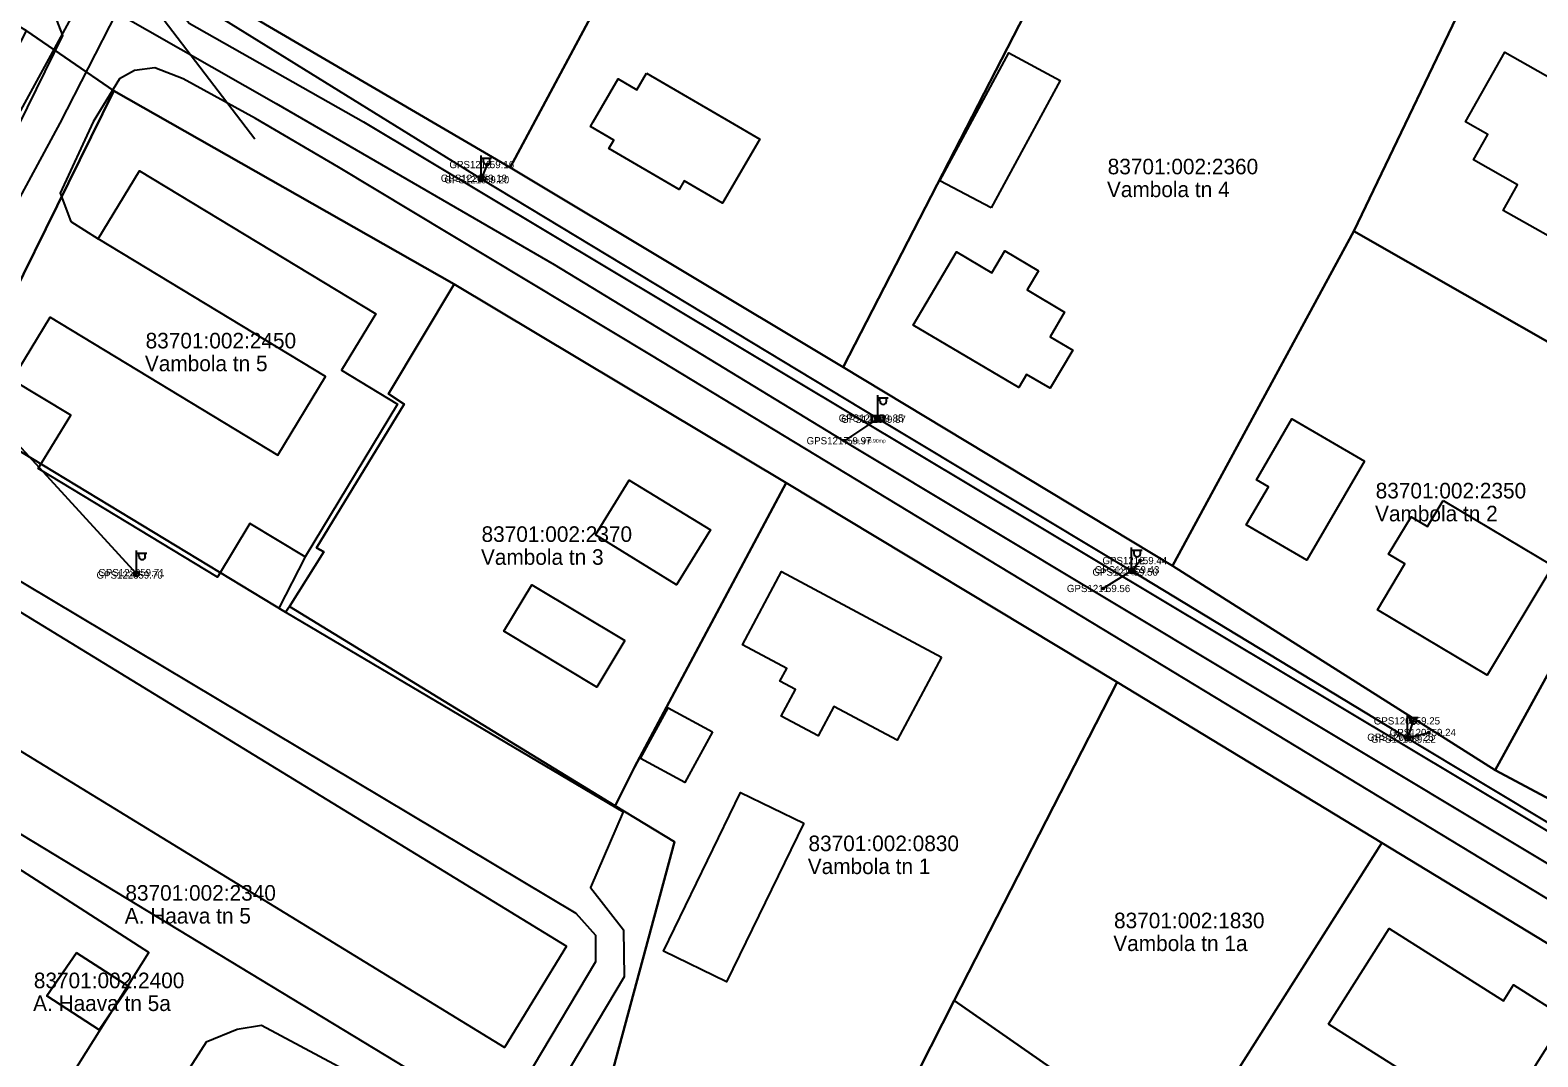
# Model space of a CAD drawing. Extents: x 580119 to 583377, y 6518915 to 6520820.
# Drawn here: x 581801.1 to 581946.3, y 6519909.9 to 6520008.8 of the extents above; entities that cross this region are included whole.
import ezdxf

# ---------------------------------------------------------------- set-up
doc = ezdxf.new("R2010")
doc.units = 0
for name, color, linetype in [('ELRAJATISMP', 7, 'Continuous'), ('Hoone Elu- või ühiskondlik hoone', 7, 'Continuous'), ('Hoone Kõrval- või tootmishoone', 7, 'Continuous'), ('L_AADRESS', 7, 'Continuous'), ('MOOTKORG-EH2000', 7, 'Continuous'), ('MOOTMPUNKT', 7, 'Continuous'), ('MOOTNR', 7, 'Continuous'), ('MPOHULIIN', 7, 'Continuous'), ('PIIR', 7, 'Continuous'), ('POST', 7, 'Continuous'), ('Rippe kõrgus', 7, 'Continuous'), ('SIOHULIIN', 7, 'Continuous'), ('Tee Liiklusala', 7, 'Continuous'), ('Tee Tänav Püsikate', 7, 'Continuous'), ('TUNNUS', 7, 'Continuous')]:
    doc.layers.add(name, color=color, linetype=linetype)

msp = doc.modelspace()

# ---------------------------------------------------------------- linework, layer by layer
at = {"layer": 'ELRAJATISMP'}
for p, q in [((581882.58, 6519971.7), (581882.58, 6519971.1)), ((581882.85, 6519971.7), (581882.85, 6519971.1))]:
    msp.add_line(p, q, dxfattribs=at)
msp.add_lwpolyline([(581882.12, 6519971.7), (581883.31, 6519971.7), (581883.31, 6519971.1), (581882.12, 6519971.1)], close=True, dxfattribs=at)
at = {"layer": 'Hoone Elu- või ühiskondlik hoone'}
for points in [[(581960.08, 6519997.16), (581954.67, 6519987.57), (581951.57, 6519989.32), (581950.41, 6519987.27), (581942.97, 6519991.47), (581944.36, 6519993.95), (581940.12, 6519996.34), (581941.5, 6519998.79), (581939.36, 6520000), (581943.16, 6520006.72)], [(581860.43, 6520004.7), (581868.5, 6520000), (581871.35, 6519998.34), (581867.76, 6519992.17), (581864.06, 6519994.32), (581863.58, 6519993.5), (581856.81, 6519997.44), (581857.28, 6519998.25), (581855.04, 6519999.56), (581855.3, 6520000), (581857.7, 6520004.14), (581859.5, 6520003.1)], [(581898.22, 6519985.66), (581897.13, 6519983.8), (581900.73, 6519981.67), (581899.33, 6519979.29), (581901.51, 6519978.01), (581899.34, 6519974.34), (581897.07, 6519975.67), (581896.31, 6519974.4), (581886.14, 6519980.41), (581890.3, 6519987.47), (581893.72, 6519985.46), (581894.97, 6519987.57)], [(581855.52, 6519960.19), (581858.78, 6519965.48), (581866.6, 6519960.67), (581863.34, 6519955.38)], [(581937.19, 6519963.52), (581947.76, 6519957.2), (581941.46, 6519946.66), (581930.88, 6519952.98), (581933.52, 6519957.4), (581931.95, 6519958.33), (581934.12, 6519961.94), (581935.69, 6519961)], [(581852.73, 6519920.56), (581846.76, 6519910.8), (581783.92, 6519949.26), (581789.88, 6519959.02)], [(581888.88, 6519948.42), (581884.6, 6519940.41), (581878.5, 6519943.66), (581876.98, 6519940.82), (581873.42, 6519942.72), (581874.79, 6519945.28), (581873.29, 6519946.08), (581873.95, 6519947.31), (581869.68, 6519949.6), (581873.45, 6519956.66)], [(581926.17, 6519913.04), (581932.01, 6519922.25), (581943.01, 6519915.28), (581943.98, 6519916.81), (581948.99, 6519913.64), (581941.79, 6519902.28), (581936.59, 6519905.58), (581936.98, 6519906.19)]]:
    msp.add_lwpolyline(points, close=True, dxfattribs=at)
at = {"layer": 'Hoone Kõrval- või tootmishoone'}
for points in [[(581893.66, 6519991.73), (581888.7, 6519994.33), (581895.37, 6520006.65), (581900.29, 6520003.98)], [(581836.46, 6519972.8), (581827.54, 6519958.08), (581822.23, 6519961.3), (581819.1, 6519956.12), (581801.84, 6519966.59), (581804.96, 6519971.72), (581799.32, 6519975.14), (581802.98, 6519981.17), (581824.91, 6519967.87), (581829.5, 6519975.45), (581807.61, 6519988.72), (581811.58, 6519995.28), (581834.35, 6519981.49), (581831.07, 6519976.07)], [(581929.63, 6519967.29), (581924.07, 6519957.75), (581918.21, 6519961.16), (581920.36, 6519964.84), (581919.21, 6519965.5), (581922.63, 6519971.37)], [(581858.36, 6519950), (581855.67, 6519945.51), (581846.7, 6519950.91), (581849.4, 6519955.37)], [(581866.8, 6519941.21), (581864.13, 6519936.33), (581859.86, 6519938.65), (581862.52, 6519943.53)], [(581875.6, 6519932.4), (581868.16, 6519917.11), (581862.07, 6519920.08), (581869.5, 6519935.37)]]:
    msp.add_lwpolyline(points, close=True, dxfattribs=at)
at = {"layer": 'MOOTMPUNKT'}
for centre in [(581845.09, 6519995.88), (581844.4, 6519994.57), (581844.61, 6519994.43), (581882.6, 6519971.45), (581882.83, 6519971.34), (581879.51, 6519969.27), (581908.01, 6519957.72), (581811.23, 6519956.33), (581811.4, 6519956.56), (581907.12, 6519956.61), (581907.26, 6519956.83), (581904.45, 6519955.03), (581934.3, 6519942.27), (581935.83, 6519941.15), (581933.67, 6519940.69), (581933.89, 6519940.51)]:
    msp.add_circle(centre, 0.1, dxfattribs=at)
at = {"layer": 'MPOHULIIN'}
for p, q in [((581808.67, 6520016.76), (581789.01, 6519980.76)), ((581845.09, 6519995.88), (581844.51, 6519994.5)), ((581789.01, 6519980.76), (581811.31, 6519956.44)), ((581882.72, 6519971.4), (581879.51, 6519969.27))]:
    msp.add_line(p, q, dxfattribs=at)
for points in [[(581808.67, 6520016.76), (581844.51, 6519994.5), (581882.72, 6519971.4), (581907.19, 6519956.72), (581933.78, 6519940.6), (581962.41, 6519923.38)], [(581934.3, 6519942.27), (581933.78, 6519940.6), (581935.83, 6519941.15)]]:
    msp.add_lwpolyline(points, dxfattribs=at)
at = {"layer": 'PIIR'}
for points in [[(581684.97, 6520093.06), (581696.38, 6520086.78), (581714.09, 6520075.87), (581741.76, 6520059.15), (581768.53, 6520042.82), (581786.85, 6520031.7), (581808.31, 6520018.92), (581818.25, 6520012.64), (581847.29, 6519995.61), (581879.39, 6519976.36), (581911.11, 6519957.21), (581942.22, 6519937.53), (581960.1, 6519927.96)], [(581958.54, 6519913.98), (581931.29, 6519930.51), (581905.78, 6519945.99), (581873.9, 6519965.21), (581841.9, 6519984.36), (581809.12, 6520003), (581800.7, 6520008.77), (581766.94, 6520028.96), (581735.46, 6520047.82), (581689.7, 6520075.34)]]:
    msp.add_lwpolyline(points, dxfattribs=at)
for points in [[(581888.28, 6520072.43), (581876.44, 6520050.07), (581847.29, 6519995.61), (581818.25, 6520012.64), (581855.23, 6520085.11), (581858.5, 6520085.99)], [(581876.44, 6520050.07), (581908.22, 6520032.46), (581879.39, 6519976.36), (581847.29, 6519995.61)], [(581908.22, 6520032.46), (581917.35, 6520027.64), (581940.76, 6520014.9), (581928.6, 6519989.46), (581911.11, 6519957.21), (581879.39, 6519976.36)], [(581940.76, 6520014.9), (581943.51, 6520012.98), (581949.86, 6520009.55), (581975.86, 6519995.13), (581974.28, 6519992.2), (581970.31, 6519984.96), (581962.19, 6519970.41), (581960.69, 6519971.17), (581928.6, 6519989.46)], [(581720.83, 6519828.38), (581713.07, 6519832.45), (581737.53, 6519880.2), (581748.92, 6519902.42), (581757.99, 6519920.64), (581755.25, 6519922.18), (581764.91, 6519940.51), (581783.47, 6519975.44), (581800.7, 6520008.77), (581809.12, 6520003), (581793.83, 6519972.03), (581765.99, 6519918.16), (581756.25, 6519899.32)], [(581809.12, 6520003), (581841.9, 6519984.36), (581835.59, 6519973.78), (581837.08, 6519972.81), (581828.64, 6519958.96), (581829.36, 6519958.56), (581826.05, 6519953.3), (581825.66, 6519952.76), (581793.83, 6519972.03)], [(581928.6, 6519989.46), (581960.69, 6519971.17), (581942.22, 6519937.53), (581911.11, 6519957.21)], [(581960.69, 6519971.17), (581962.19, 6519970.41), (581970.31, 6519984.96), (581988.02, 6519974.12), (581960.1, 6519927.96), (581942.22, 6519937.53)], [(581829.36, 6519958.56), (581828.64, 6519958.96), (581837.08, 6519972.81), (581835.59, 6519973.78), (581841.9, 6519984.36), (581873.9, 6519965.21), (581859.27, 6519937.79), (581857.43, 6519934.09), (581826.05, 6519953.3)], [(581793.83, 6519972.03), (581825.66, 6519952.76), (581826.05, 6519953.3), (581857.43, 6519934.09), (581863.13, 6519930.6), (581856.71, 6519906.79), (581852.12, 6519905.22), (581837.88, 6519900.5), (581828.31, 6519877.26), (581797.75, 6519897.83), (581797.87, 6519898.15), (581765.99, 6519918.16)], [(581863.13, 6519930.6), (581857.43, 6519934.09), (581859.27, 6519937.79), (581873.9, 6519965.21), (581905.78, 6519945.99), (581890.08, 6519915.3), (581884.43, 6519904.17), (581879.52, 6519894.73), (581856.71, 6519906.79)], [(581905.78, 6519945.99), (581931.29, 6519930.51), (581912, 6519900.05), (581890.08, 6519915.3)], [(581931.29, 6519930.51), (581958.54, 6519913.98), (581937.23, 6519884.02), (581912, 6519900.05)], [(581805.51, 6519919.92), (581802.65, 6519915.77), (581807.7, 6519912.5), (581810.56, 6519916.65)], [(581805.51, 6519919.92), (581810.56, 6519916.65), (581807.7, 6519912.5), (581802.65, 6519915.77)], [(581890.08, 6519915.3), (581912, 6519900.05), (581937.23, 6519884.02), (581950.04, 6519875.88), (581942.99, 6519865.51), (581908.42, 6519888.38), (581884.43, 6519904.17)]]:
    msp.add_lwpolyline(points, close=True, dxfattribs=at)
at = {"layer": 'POST'}
for p, q in [((581844.51, 6519994.75), (581844.51, 6519996.75)), ((581844.51, 6519996.5), (581845.51, 6519996.5)), ((581844.73, 6519996.18), (581844.73, 6519996.5)), ((581845.35, 6519996.18), (581845.35, 6519996.5)), ((581844.51, 6519994.5), (581844.51, 6519994.5)), ((581882.72, 6519971.65), (581882.72, 6519973.65)), ((581882.72, 6519973.4), (581883.72, 6519973.4)), ((581882.94, 6519973.08), (581882.94, 6519973.4)), ((581883.56, 6519973.08), (581883.56, 6519973.4)), ((581882.72, 6519971.4), (581882.72, 6519971.4)), ((581811.31, 6519956.69), (581811.31, 6519958.69)), ((581907.19, 6519956.97), (581907.19, 6519958.97)), ((581907.19, 6519958.72), (581908.19, 6519958.72)), ((581907.42, 6519958.4), (581907.42, 6519958.72)), ((581908.03, 6519958.4), (581908.03, 6519958.72)), ((581811.31, 6519958.44), (581812.31, 6519958.44)), ((581811.54, 6519958.12), (581811.54, 6519958.44)), ((581812.15, 6519958.12), (581812.15, 6519958.44)), ((581811.31, 6519956.44), (581811.31, 6519956.44)), ((581907.19, 6519956.72), (581907.19, 6519956.72)), ((581933.78, 6519940.85), (581933.78, 6519942.85)), ((581933.78, 6519942.6), (581934.78, 6519942.6)), ((581934.01, 6519942.28), (581934.01, 6519942.6)), ((581934.62, 6519942.28), (581934.62, 6519942.6)), ((581933.78, 6519940.6), (581933.78, 6519940.6))]:
    msp.add_line(p, q, dxfattribs=at)
for centre, radius in [((581844.51, 6519994.5), 0.25), ((581882.72, 6519971.4), 0.25), ((581811.31, 6519956.44), 0.25), ((581811.31, 6519956.44), 0.0234), ((581907.19, 6519956.72), 0.25), ((581933.78, 6519940.6), 0.25)]:
    msp.add_circle(centre, radius, dxfattribs=at)
for centre in [(581845.04, 6519996.18), (581883.25, 6519973.08), (581811.85, 6519958.12), (581907.72, 6519958.4), (581934.32, 6519942.28)]:
    msp.add_arc(centre, 0.306, 180, 0, dxfattribs=at)
at = {"layer": 'SIOHULIIN'}
msp.add_line((581907.19, 6519956.72), (581908.01, 6519957.72), dxfattribs=at)
for points in [[(581822.71, 6519998.33), (581808.67, 6520016.76), (581805.93, 6520029.56)], [(581934.3, 6519942.27), (581933.78, 6519940.6), (581907.19, 6519956.72), (581904.45, 6519955.03)]]:
    msp.add_lwpolyline(points, dxfattribs=at)
at = {"layer": 'Tee Liiklusala'}
for points in [[(581951.62, 6520039.93), (581930.6, 6520052.21), (581908.83, 6520065.92), (581904.46, 6520069.5), (581880.48, 6520080.92), (581860.65, 6520089.71), (581856.97, 6520089.65), (581853.65, 6520088.44), (581850.79, 6520086.07), (581846.57, 6520077.86), (581840.27, 6520065.98), (581832.9, 6520051.3), (581814.42, 6520014.83), (581814.49, 6520011.91), (581816.36, 6520009.51), (581833.17, 6520000), (581968.76, 6519918.78)], [(581966.62, 6519913.35), (581860.94, 6519977.48), (581845.13, 6519986.99), (581830.77, 6519995.63), (581822.76, 6520000.33), (581815.8, 6520004.15), (581813.08, 6520005.2), (581811.12, 6520004.96), (581809.65, 6520004.14), (581807.12, 6520000), (581803.94, 6519993.12), (581804.99, 6519990.4), (581807.61, 6519988.72), (581811.58, 6519995.28), (581834.35, 6519981.49), (581831.07, 6519976.07), (581836.46, 6519972.8), (581827.54, 6519958.08), (581825.01, 6519953.14), (581858.2, 6519933.49), (581855.05, 6519926.2), (581858.21, 6519922.14), (581858.29, 6519917.59), (581852.27, 6519907.51)], [(581839.03, 6519824.04), (581826.18, 6519830.38), (581817.04, 6519834.89), (581809.33, 6519839.02), (581813.06, 6519846.73), (581828.27, 6519877.99), (581838.26, 6519897.92), (581838.85, 6519901.47), (581837.67, 6519903.83), (581835.9, 6519906.19), (581823.35, 6519912.9), (581820.99, 6519912.53), (581818, 6519911.29), (581811.22, 6519900.66), (581803.77, 6519906.09), (581812.48, 6519919.95), (581785.21, 6519937.48)]]:
    msp.add_lwpolyline(points, dxfattribs=at)
msp.add_lwpolyline([(581788.3, 6519976.59), (581799.97, 6519999.69), (581804.21, 6520008.32), (581803.44, 6520010.33), (581801.94, 6520011.85), (581739.51, 6520050.52), (581694.43, 6520077.93), (581691.68, 6520078.4), (581688.58, 6520078.18), (581685.98, 6520077.01), (581668.05, 6520046.79), (581701.95, 6520026.49), (581706.12, 6520016.42), (581714.87, 6520011.61), (581717.12, 6520014.42), (581746.56, 6519997.05), (581745.97, 6519996.01), (581782.53, 6519973.29), (581784.91, 6519972.79), (581786.92, 6519974.64)], close=True, dxfattribs=at)
at = {"layer": 'Tee Tänav Püsikate'}
for points in [[(581809.38, 6520010.54), (581803.92, 6519999.89), (581784.93, 6519964.78)], [(581809.38, 6520010.54), (581824.75, 6520001.77), (581827.81, 6520000), (581851.56, 6519986.25), (581879.97, 6519968.93), (581967.05, 6519916.64), (582003.51, 6519892.41)], [(581784.93, 6519964.78), (581787.12, 6519963.47), (581853.62, 6519923.72), (581855.53, 6519921.6), (581855.53, 6519919.04), (581849.52, 6519908.96)], [(581849.52, 6519908.96), (581846.2, 6519903.41), (581775.42, 6519946.31)]]:
    msp.add_lwpolyline(points, dxfattribs=at)

# ---------------------------------------------------------------- texts
at = {"layer": 'L_AADRESS'}
for s, p in [('Vambola tn 4', (581904.81, 6519992.75)), ('Vambola tn 5', (581812.11, 6519975.97)), ('Vambola tn 2', (581930.64, 6519961.5)), ('Vambola tn 3', (581844.49, 6519957.31)), ('Vambola tn 1', (581875.98, 6519927.5)), ('A. Haava tn 5', (581810.17, 6519922.73)), ('Vambola tn 1a', (581905.42, 6519920.08)), ('A. Haava tn 5a', (581801.34, 6519914.3))]:
    msp.add_text(s, height=1.5, dxfattribs=at).set_placement(p)
at = {"layer": 'MOOTKORG-EH2000'}
for s, p in [(' 59.16', (581845.09, 6519995.54)), (' 59.19', (581844.4, 6519994.22)), (' 59.20', (581844.61, 6519994.08)), (' 59.85', (581882.6, 6519971.1)), (' 59.87', (581882.83, 6519970.99)), (' 59.97', (581879.51, 6519968.92)), (' 59.43', (581907.26, 6519956.48)), (' 59.44', (581908.01, 6519957.37)), (' 59.70', (581811.23, 6519955.98)), (' 59.71', (581811.4, 6519956.21)), (' 59.50', (581907.12, 6519956.26)), (' 59.56', (581904.45, 6519954.68)), (' 59.25', (581934.3, 6519941.92)), (' 59.24', (581935.83, 6519940.8)), (' 59.25', (581933.67, 6519940.34)), (' 59.22', (581933.89, 6519940.16))]:
    msp.add_text(s, height=0.7, dxfattribs=at).set_placement(p)
at = {"layer": 'MOOTNR'}
for s, p in [('GPS1218 ', (581841.45, 6519995.54)), ('GPS1220 ', (581840.62, 6519994.22)), ('GPS1219 ', (581840.97, 6519994.08)), ('GPS1216 ', (581878.96, 6519971.1)), ('GPS1215 ', (581879.2, 6519970.99)), ('GPS1217 ', (581875.87, 6519968.92)), ('GPS1213 ', (581903.62, 6519956.48)), ('GPS1212 ', (581904.37, 6519957.37)), ('GPS1228 ', (581807.45, 6519955.98)), ('GPS1229 ', (581807.62, 6519956.21)), ('GPS1214 ', (581903.41, 6519956.26)), ('GPS1211 ', (581900.95, 6519954.68)), ('GPS1208 ', (581930.52, 6519941.92)), ('GPS1207 ', (581932.05, 6519940.8)), ('GPS1209 ', (581929.89, 6519940.34)), ('GPS1210 ', (581930.25, 6519940.16))]:
    msp.add_text(s, height=0.7, dxfattribs=at).set_placement(p)
at = {"layer": 'Rippe kõrgus'}
msp.add_text(' el_mp_ohl5.90mp', height=0.35, dxfattribs=at).set_placement((581879.51, 6519969.09))
at = {"layer": 'TUNNUS'}
for s, p in [('83701:002:2360', (581904.88, 6519994.95)), ('83701:002:2450', (581812.18, 6519978.17)), ('83701:002:2350', (581930.7, 6519963.71)), ('83701:002:2370', (581844.55, 6519959.52)), ('83701:002:0830', (581876.05, 6519929.71)), ('83701:002:2340', (581810.23, 6519924.94)), ('83701:002:1830', (581905.49, 6519922.28)), ('83701:002:2400', (581801.41, 6519916.5))]:
    msp.add_text(s, height=1.5, dxfattribs=at).set_placement(p)

doc.saveas('drawing.dxf')
